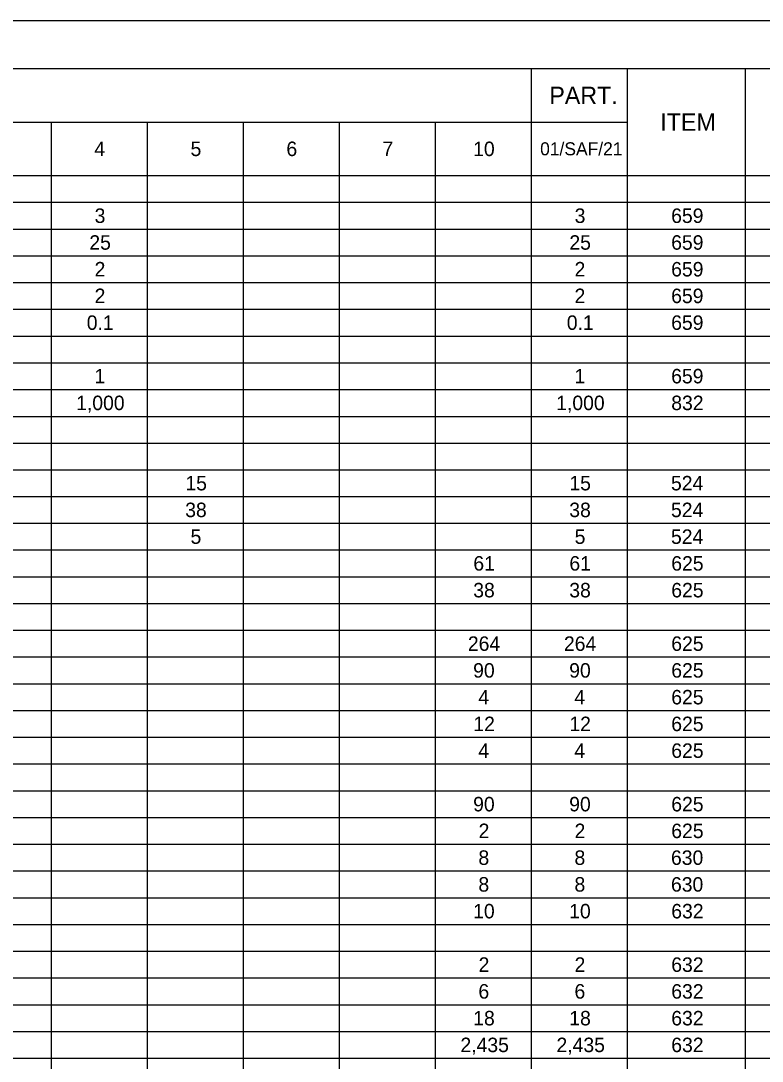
# Model space of a CAD drawing. Extents: x 0 to 34, y 0 to 22.
# Drawn here: x 9.22 to 16.98, y 11.11 to 22 of the extents above; entities that cross this region are included whole.
import ezdxf

# ---------------------------------------------------------------- set-up
doc = ezdxf.new("R2010")
doc.units = 0
for name, color, linetype in [('Default', 7, 'Continuous'), ('SH_Border', 7, 'Continuous'), ('SH_Cut_Line', 7, 'Continuous')]:
    doc.layers.add(name, color=color, linetype=linetype)

msp = doc.modelspace()

# ---------------------------------------------------------------- linework, layer by layer
at = {"layer": 'Default'}
for p, q in [((1.5, 21.5), (32, 21.5)), ((14.56, 21.5), (14.56, 0.502)), ((15.564, 21.5), (15.564, 0.502)), ((16.799, 21.5), (16.799, 0.502)), ((1.5, 20.94), (15.564, 20.94)), ((9.537, 20.94), (9.537, 0.502)), ((10.541, 20.94), (10.541, 0.502)), ((11.546, 20.94), (11.546, 0.502)), ((12.55, 20.94), (12.55, 0.502)), ((13.555, 20.94), (13.555, 0.502)), ((1.5, 20.38), (32, 20.38)), ((1.5, 20.1), (32, 20.1)), ((1.5, 19.82), (32, 19.82)), ((1.5, 19.54), (32, 19.54)), ((1.5, 19.26), (32, 19.26)), ((1.5, 18.98), (32, 18.98)), ((1.5, 18.7), (32, 18.7)), ((1.5, 18.42), (32, 18.42)), ((1.5, 18.14), (32, 18.14)), ((1.5, 17.86), (32, 17.86)), ((1.5, 17.58), (32, 17.58)), ((1.5, 17.3), (32, 17.3)), ((1.5, 17.021), (32, 17.021)), ((1.5, 16.741), (32, 16.741)), ((1.5, 16.461), (32, 16.461)), ((1.5, 16.181), (32, 16.181)), ((1.5, 15.901), (32, 15.901)), ((1.5, 15.621), (32, 15.621)), ((1.5, 15.341), (32, 15.341)), ((1.5, 15.061), (32, 15.061)), ((1.5, 14.781), (32, 14.781)), ((1.5, 14.501), (32, 14.501)), ((1.5, 14.221), (32, 14.221)), ((1.5, 13.941), (32, 13.941)), ((1.5, 13.661), (32, 13.661)), ((1.5, 13.381), (32, 13.381)), ((1.5, 13.101), (32, 13.101)), ((1.5, 12.821), (32, 12.821)), ((1.5, 12.541), (32, 12.541)), ((1.5, 12.261), (32, 12.261)), ((1.5, 11.981), (32, 11.981)), ((1.5, 11.701), (32, 11.701)), ((1.5, 11.421), (32, 11.421)), ((1.5, 11.141), (32, 11.141))]:
    msp.add_line(p, q, dxfattribs=at)
at = {"layer": 'SH_Border'}
msp.add_lwpolyline([(1.5, 21.5), (33.5, 21.5), (33.5, 0.5), (1.5, 0.5)], close=True, dxfattribs=at)
at = {"layer": 'SH_Cut_Line'}
msp.add_lwpolyline([(0, 0), (34, 0), (34, 22), (0, 22)], close=True, dxfattribs=at)

# ---------------------------------------------------------------- texts
at = {"layer": 'Default'}
for s, height, p in [('PART.', 0.1818, (14.749, 21.129)), ('ITEM', 0.1818, (15.91, 20.849)), ('4', 0.152, (9.988, 20.584)), ('5', 0.152, (10.995, 20.584)), ('6', 0.152, (11.998, 20.584)), ('7', 0.152, (13.003, 20.584)), ('10', 0.1515, (13.952, 20.584)), ('01/SAF/21', 0.1364, (14.653, 20.592)), ('3', 0.152, (9.991, 19.884)), ('3', 0.152, (15.014, 19.884)), ('659', 0.1515, (16.024, 19.884)), ('25', 0.1515, (9.936, 19.604)), ('25', 0.1515, (14.959, 19.604)), ('659', 0.1515, (16.024, 19.604)), ('2', 0.152, (9.991, 19.324)), ('2', 0.152, (15.013, 19.324)), ('659', 0.1515, (16.024, 19.324)), ('2', 0.152, (9.991, 19.045)), ('2', 0.152, (15.013, 19.045)), ('659', 0.1515, (16.024, 19.045)), ('0.1', 0.1515, (9.909, 18.765)), ('0.1', 0.1515, (14.932, 18.765)), ('659', 0.1515, (16.024, 18.765)), ('1', 0.152, (9.99, 18.205)), ('1', 0.152, (15.013, 18.205)), ('659', 0.1515, (16.024, 18.205)), ('1,000', 0.1515, (9.798, 17.925)), ('1,000', 0.1515, (14.821, 17.925)), ('832', 0.1515, (16.025, 17.925)), ('15', 0.1515, (10.941, 17.085)), ('15', 0.1515, (14.959, 17.085)), ('524', 0.1515, (16.022, 17.085)), ('38', 0.1515, (10.939, 16.805)), ('38', 0.1515, (14.958, 16.805)), ('524', 0.1515, (16.022, 16.805)), ('5', 0.152, (10.995, 16.525)), ('5', 0.152, (15.014, 16.525)), ('524', 0.1515, (16.022, 16.525)), ('61', 0.1515, (13.954, 16.245)), ('61', 0.1515, (14.959, 16.245)), ('625', 0.1515, (16.025, 16.245)), ('38', 0.1515, (13.953, 15.965)), ('38', 0.1515, (14.958, 15.965)), ('625', 0.1515, (16.025, 15.965)), ('264', 0.1515, (13.897, 15.405)), ('264', 0.1515, (14.902, 15.405)), ('625', 0.1515, (16.025, 15.405)), ('90', 0.1515, (13.952, 15.125)), ('90', 0.1515, (14.957, 15.125)), ('625', 0.1515, (16.025, 15.125)), ('4', 0.152, (14.006, 14.845)), ('4', 0.152, (15.011, 14.845)), ('625', 0.1515, (16.025, 14.845)), ('12', 0.1515, (13.954, 14.565)), ('12', 0.1515, (14.959, 14.565)), ('625', 0.1515, (16.025, 14.565)), ('4', 0.152, (14.006, 14.285)), ('4', 0.152, (15.011, 14.285)), ('625', 0.1515, (16.025, 14.285)), ('90', 0.1515, (13.952, 13.725)), ('90', 0.1515, (14.957, 13.725)), ('625', 0.1515, (16.025, 13.725)), ('2', 0.152, (14.009, 13.445)), ('2', 0.152, (15.013, 13.445)), ('625', 0.1515, (16.025, 13.445)), ('8', 0.152, (14.007, 13.165)), ('8', 0.152, (15.012, 13.165)), ('630', 0.1515, (16.022, 13.165)), ('8', 0.152, (14.007, 12.885)), ('8', 0.152, (15.012, 12.885)), ('630', 0.1515, (16.022, 12.885)), ('10', 0.1515, (13.952, 12.605)), ('10', 0.1515, (14.957, 12.605)), ('632', 0.1515, (16.025, 12.605)), ('2', 0.152, (14.009, 12.045)), ('2', 0.152, (15.013, 12.045)), ('632', 0.1515, (16.025, 12.045)), ('6', 0.152, (14.007, 11.765)), ('6', 0.152, (15.012, 11.765)), ('632', 0.1515, (16.025, 11.765)), ('18', 0.1515, (13.953, 11.485)), ('18', 0.1515, (14.958, 11.485)), ('632', 0.1515, (16.025, 11.485)), ('2,435', 0.1515, (13.819, 11.205)), ('2,435', 0.1515, (14.824, 11.205)), ('632', 0.1515, (16.025, 11.205))]:
    msp.add_text(s, height=height, dxfattribs=at).set_placement(p)

doc.saveas('drawing.dxf')
